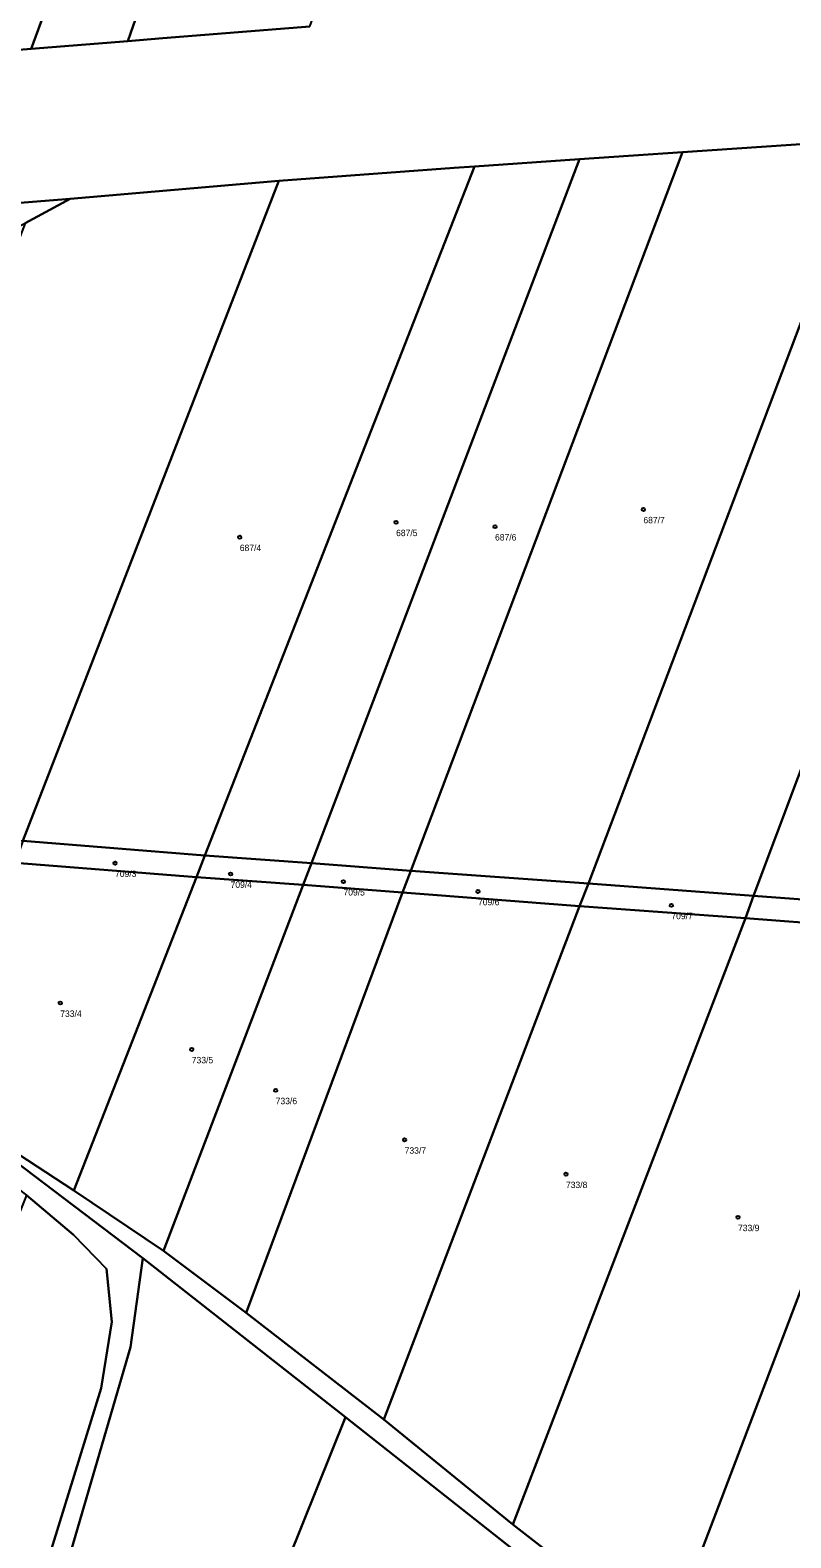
# Model space of a CAD drawing. Extents: x -587171 to -555306, y -1167727 to -1074732.
# Drawn here: x -585640.5 to -585521.6, y -1166041.5 to -1165806 of the extents above; entities that cross this region are included whole.
import ezdxf

# ---------------------------------------------------------------- set-up
doc = ezdxf.new("R2010")
doc.units = 0
doc.layers.add('Definiční body', color=7, linetype='Continuous')
doc.layers.add('Polygon parcely', color=7, linetype='Continuous')

msp = doc.modelspace()

# ---------------------------------------------------------------- linework, layer by layer
at = {"layer": 'Definiční body'}
for centre in [(-585583.31, -1165882.84), (-585544.67, -1165880.83), (-585607.73, -1165885.17), (-585567.85, -1165883.52), (-585627.22, -1165936.08), (-585609.17, -1165937.78), (-585591.53, -1165938.97), (-585570.51, -1165940.5), (-585540.3, -1165942.67), (-585635.78, -1165957.93), (-585615.23, -1165965.18), (-585602.12, -1165971.57), (-585581.97, -1165979.3), (-585556.77, -1165984.67), (-585529.89, -1165991.4)]:
    msp.add_circle(centre, 0.25, dxfattribs=at)
at = {"layer": 'Polygon parcely'}
for points in [[(-585658.95, -1165810.4), (-585640.31, -1165808.9), (-585627.6, -1165774.32), (-585642.37, -1165768.65)], [(-585640.31, -1165808.9), (-585625.24, -1165807.66), (-585613.61, -1165774.3), (-585626.1, -1165770.23), (-585627.6, -1165774.32)], [(-585596.77, -1165805.42), (-585588.73, -1165782.98), (-585613.61, -1165774.3), (-585625.24, -1165807.66), (-585619.73, -1165807.2)], [(-585527.46, -1165941.19), (-585497.38, -1165943.4), (-585449.54, -1165818.42), (-585482.34, -1165821.19)], [(-585553.22, -1165939.28), (-585527.46, -1165941.19), (-585482.34, -1165821.19), (-585509.22, -1165823.03)], [(-585581.01, -1165937.28), (-585553.22, -1165939.28), (-585509.22, -1165823.03), (-585538.56, -1165825.04)], [(-585613.18, -1165934.86), (-585596.51, -1165936.07), (-585554.63, -1165826.13), (-585571.06, -1165827.26)], [(-585538.56, -1165825.04), (-585554.63, -1165826.13), (-585596.51, -1165936.07), (-585581.01, -1165937.28)], [(-585571.06, -1165827.26), (-585574.23, -1165827.48), (-585601.64, -1165829.48), (-585641.63, -1165932.57), (-585613.18, -1165934.86)], [(-585601.64, -1165829.48), (-585634.24, -1165832.33), (-585641.27, -1165836.1), (-585677.41, -1165930.03), (-585641.63, -1165932.57)], [(-585644.54, -1165837.77), (-585641.27, -1165836.1), (-585634.24, -1165832.33), (-585655.79, -1165834.03), (-585661.69, -1165837.97), (-585667.19, -1165850.25), (-585658.98, -1165849.16)], [(-585614.51, -1165938.25), (-585613.18, -1165934.86), (-585641.63, -1165932.57), (-585642.8, -1165936.02)], [(-585614.51, -1165938.25), (-585642.8, -1165936.02), (-585656.76, -1165972.11), (-585633.67, -1165987.2)], [(-585597.81, -1165939.49), (-585596.51, -1165936.07), (-585613.18, -1165934.86), (-585614.51, -1165938.25)], [(-585581.01, -1165937.28), (-585596.51, -1165936.07), (-585597.81, -1165939.49), (-585582.33, -1165940.68)], [(-585619.63, -1165996.62), (-585597.81, -1165939.49), (-585614.51, -1165938.25), (-585633.67, -1165987.2)], [(-585554.64, -1165942.82), (-585553.22, -1165939.28), (-585581.01, -1165937.28), (-585582.33, -1165940.68)], [(-585528.72, -1165944.69), (-585527.46, -1165941.19), (-585553.22, -1165939.28), (-585554.64, -1165942.82)], [(-585582.33, -1165940.68), (-585597.81, -1165939.49), (-585619.63, -1165996.62), (-585606.74, -1166006.31)], [(-585554.64, -1165942.82), (-585582.33, -1165940.68), (-585606.74, -1166006.31), (-585585.24, -1166022.98)], [(-585497.38, -1165943.4), (-585527.46, -1165941.19), (-585528.72, -1165944.69), (-585498.83, -1165946.97)], [(-585565.07, -1166039.39), (-585528.72, -1165944.69), (-585554.64, -1165942.82), (-585585.24, -1166022.98)], [(-585541.09, -1166058.04), (-585498.83, -1165946.97), (-585528.72, -1165944.69), (-585565.07, -1166039.39)], [(-585468.09, -1165948.75), (-585489.17, -1165947.67), (-585498.83, -1165946.97), (-585541.09, -1166058.04), (-585517, -1166077.05)], [(-585697.57, -1166186.15), (-585685.24, -1166163.9), (-585672.28, -1166135.9), (-585658.71, -1166106.18), (-585639.38, -1166050.43), (-585629.41, -1166018.09), (-585627.74, -1166007.71), (-585628.54, -1165999.45), (-585633.7, -1165994.13), (-585641.06, -1165987.95), (-585695.64, -1166124.76), (-585746.15, -1166252.04), (-585792.93, -1166369.09), (-585785.16, -1166374.4), (-585771.47, -1166387.86), (-585760.73, -1166347.69), (-585753.1, -1166320.6), (-585744.73, -1166294.85), (-585715.71, -1166223.84)], [(-585681.9, -1166247.57), (-585638.12, -1166139.35), (-585591.19, -1166022.61), (-585622.9, -1165997.8), (-585624.81, -1166011.66), (-585639.27, -1166061.26), (-585654.86, -1166106.88), (-585673.43, -1166148.71), (-585690.9, -1166179.9), (-585708.51, -1166218.49), (-585702.54, -1166224.96), (-585694.06, -1166234.36), (-585685.91, -1166243.26)], [(-585607.48, -1166170.24), (-585558.35, -1166048.55), (-585591.19, -1166022.61), (-585638.12, -1166139.35), (-585681.9, -1166247.57), (-585677.65, -1166252.34), (-585669.27, -1166262.42), (-585661.09, -1166272.33), (-585653.07, -1166281.94), (-585652.69, -1166282.42)]]:
    msp.add_lwpolyline(points, close=True, dxfattribs=at)
for points in [[(-585596.77, -1165805.42), (-585619.73, -1165807.2), (-585625.24, -1165807.66), (-585640.31, -1165808.9), (-585658.95, -1165810.4), (-585670.26, -1165804.71), (-585709.26, -1165819.29), (-585728.59, -1165823.68), (-585787.62, -1165842.09), (-585829.37, -1165854.4), (-585862.52, -1165861.01), (-585867.08, -1165863.32), (-585880.42, -1165869.92), (-585924.13, -1165898.32), (-586016.63, -1165942.03), (-586047.1, -1165956.01)], [(-585870.27, -1165898.87), (-585850.05, -1165893.53), (-585847.15, -1165894.58), (-585844.03, -1165897.09), (-585842.32, -1165892.13), (-585841.6, -1165889.8), (-585841.17, -1165888.52), (-585815.11, -1165874.74), (-585795.32, -1165860.24), (-585754.28, -1165848.65), (-585716.17, -1165840.28), (-585686.38, -1165834.81), (-585673.05, -1165836.56), (-585671.95, -1165836.7), (-585661.69, -1165837.97), (-585655.79, -1165834.03), (-585634.24, -1165832.33), (-585601.64, -1165829.48), (-585574.23, -1165827.48), (-585571.06, -1165827.26), (-585554.63, -1165826.13), (-585538.56, -1165825.04), (-585509.22, -1165823.03)], [(-585639.27, -1166061.26), (-585624.81, -1166011.66), (-585622.9, -1165997.8), (-585656.76, -1165972.11), (-585685.5, -1165950.98), (-585710.63, -1165931.78), (-585714.42, -1165931.59), (-585717.62, -1165931.43), (-585718.77, -1165931.37), (-585713.04, -1165935.44), (-585695.44, -1165947.93), (-585676.97, -1165961.48), (-585667.98, -1165967.84), (-585658.24, -1165974.94), (-585653.3, -1165978.63), (-585648.49, -1165982.29), (-585641.06, -1165987.95), (-585633.7, -1165994.13), (-585628.54, -1165999.45), (-585627.74, -1166007.71), (-585629.41, -1166018.09), (-585639.38, -1166050.43)], [(-585517, -1166077.05), (-585541.09, -1166058.04), (-585565.07, -1166039.39), (-585585.24, -1166022.98), (-585606.74, -1166006.31), (-585619.63, -1165996.62), (-585633.67, -1165987.2), (-585656.76, -1165972.11), (-585622.9, -1165997.8), (-585591.19, -1166022.61), (-585558.35, -1166048.55), (-585539.18, -1166063.54), (-585526.26, -1166073.82), (-585481.14, -1166108.66)]]:
    msp.add_lwpolyline(points, dxfattribs=at)

# ---------------------------------------------------------------- texts
at = {"layer": 'Definiční body'}
for s, p in [('687/7', (-585544.67, -1165882.99)), ('687/5', (-585583.31, -1165885)), ('687/6', (-585567.85, -1165885.68)), ('687/4', (-585607.73, -1165887.33)), ('709/3', (-585627.22, -1165938.24)), ('709/4', (-585609.17, -1165939.94)), ('709/5', (-585591.53, -1165941.13)), ('709/6', (-585570.51, -1165942.66)), ('709/7', (-585540.3, -1165944.83)), ('733/4', (-585635.78, -1165960.09)), ('733/5', (-585615.23, -1165967.34)), ('733/6', (-585602.12, -1165973.73)), ('733/7', (-585581.97, -1165981.46)), ('733/8', (-585556.77, -1165986.83)), ('733/9', (-585529.89, -1165993.56))]:
    msp.add_text(s, height=1, dxfattribs=at).set_placement(p)

doc.saveas('drawing.dxf')
